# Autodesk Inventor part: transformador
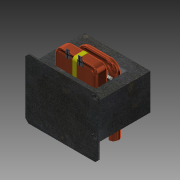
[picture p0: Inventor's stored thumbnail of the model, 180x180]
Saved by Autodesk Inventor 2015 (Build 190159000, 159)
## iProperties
Created: 2016-03
Part Number: transformador
Material: Acero
Document SubType Name: Modeling
Designer: Diego
Density: 7.85 g/cm^3
Appearance: Placa
Author: Diego
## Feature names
1. Extrusión1
2. Extrusión2
3. Empalme1 [Fillet]
4. Empalme2 [Fillet]
5. Empalme3 [Fillet]
6. Empalme4 [Fillet]
7. Empalme5 [Fillet]
8. Empalme6 [Fillet]
9. Empalme7 [Fillet]
10. Empalme8 [Fillet]
11. Extrusión3
12. Chaflán1 [Chamfer]
13. Chaflán2 [Chamfer]
14. Chaflán3 [Chamfer]
15. Chaflán4 [Chamfer]
16. Extrusión4
17. Extrusión5
18. Barrido1
19. Agujero1 [Hole]
20. Extrusión6
21. Empalme9 [Fillet]
22. Empalme10 [Fillet]
23. Extrusión7
24. Agujero2 [Hole]
25. Extrusión8
26. Agujero3 [Hole]
27. Agujero4 [Hole]
28. Agujero5 [Hole]
29. Extrusión9
30. Extrusión10
## Parameters: d0 = 105 mm, d1 = 87 mm, d2 = 19 mm, d3 = 19 mm, d6 = 16 mm, d7 = 16 mm, d8 = 57 mm, d9 = 0, d10 = 25 mm, d11 = 75 mm, d12 = 0, d13 = 0, d18 = 5 mm, d19 = 5 mm, d20 = 5 mm, d21 = 5 mm, d22 = 59 mm, d23 = 116 mm, d24 = 2 mm, d25 = 15 mm, d27 = 0, d28 = 0, d29 = 5 mm, d30 = 2 mm, d31 = 45 deg, d32 = 5 mm, d33 = 2 mm, d34 = 45 deg, d35 = 5 mm, d36 = 2 mm, d37 = 45 deg, d38 = 5 mm, d39 = 2 mm, d40 = 45 deg, d41 = 2 mm, d42 = 59 mm, d43 = 0, d44 = 0, d45 = 2 mm, d46 = 59 mm, d47 = 0, d48 = 0, d49 = 14 mm, d55 = 0, d56 = 0, d57 = 6 mm, d58 = 6 mm, d59 = 4 mm, d60 = 2 mm, d61 = 90 deg, d62 = 8 mm, d63 = 118 deg, d64 = 0.1 mm, d65 = 0, d66 = 21.1 mm, d67 = 0, d68 = 5 mm, d69 = 5 mm, d70 = 8 mm, d71 = 1 mm, d72 = 0, d75 = 2 mm, d76 = 6 mm, d77 = 4 mm, d78 = 2 mm, d79 = 90 deg, d80 = 8 mm, d81 = 118 deg, d82 = 8 mm, d83 = 8 mm, d84 = 5 mm, d85 = 1 mm, d86 = 0, d89 = 2 mm, d90 = 6 mm, d91 = 4 mm, d92 = 2 mm, d93 = 90 deg, d94 = 8 mm, d95 = 118 deg, d98 = 8 mm, d99 = 6 mm, d100 = 4 mm, d101 = 2 mm, d102 = 90 deg, d103 = 8 mm, d104 = 118 deg, d107 = 8 mm, d108 = 6 mm, d109 = 4 mm, d110 = 2 mm, d111 = 90 deg, d112 = 8 mm, d113 = 118 deg, d114 = 0.1 mm, d115 = 0, d116 = 0.1 mm, d117 = 0
